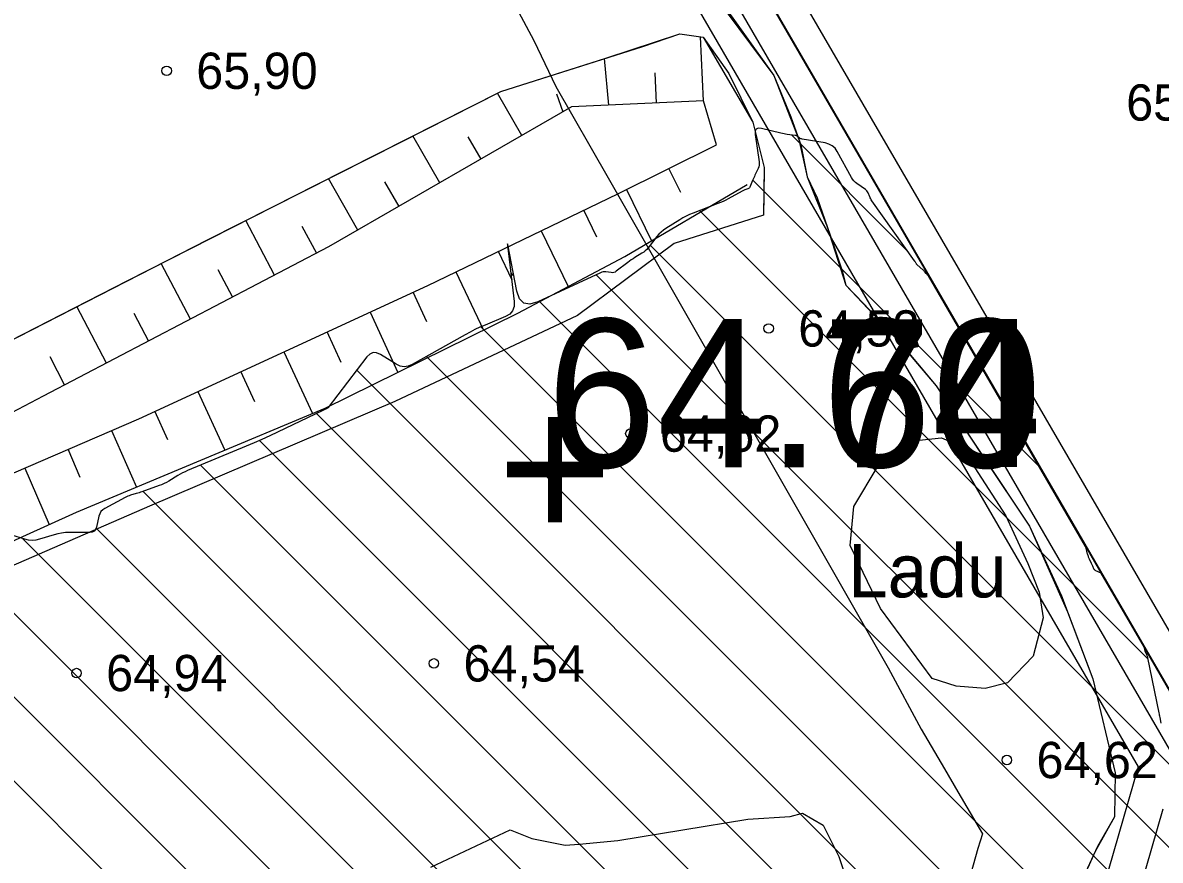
# Model space of a CAD drawing. Extents: x 532503 to 539665, y 6557663 to 6561526.
# Drawn here: x 535410.7 to 535487.5, y 6559863.4 to 6559920 of the extents above; entities that cross this region are included whole.
import ezdxf

# ---------------------------------------------------------------- set-up
doc = ezdxf.new("R2010")
doc.units = 0
for name, color, linetype in [('Default', 7, 'Continuous'), ('HALJASTUS', 7, 'Continuous'), ('illumineerimisjooned', 7, 'Continuous'), ('Kaevandatud ala', 7, 'Continuous'), ('kataster', 7, 'Continuous'), ('KORGUS-EH2000', 7, 'Continuous'), ('MOOTKORG', 7, 'Continuous'), ('MOOTKORGMUU-EH2000', 7, 'Continuous'), ('MOOTMPUNKT', 7, 'Continuous'), ('PIIR_me', 7, 'Continuous'), ('Plokid', 7, 'Continuous'), ('RELJEEF', 7, 'Continuous'), ('TM_aktiivne', 7, 'Continuous')]:
    doc.layers.add(name, color=color, linetype=linetype)

# ---------------------------------------------------------------- blocks, each defined once
blk = doc.blocks.new('POINT_DISPLAY')
at = {"layer": 'Default'}
blk.add_line((0, 0), (0, 0), dxfattribs=at)

msp = doc.modelspace()

# ---------------------------------------------------------------- linework, layer by layer
at = {"layer": 'illumineerimisjooned'}
msp.add_lwpolyline([(534195.15, 6559981.187), (534198.982, 6559981.551), (535160.123, 6560071.768), (535418.528, 6559993.818), (535458.873, 6559929.252), (535494.628, 6559867.696), (535482.599, 6559826.001), (535251.738, 6559649.676), (535250.358, 6559648.526), (535180.445, 6559687.333), (534941.147, 6559814.594), (534876.935, 6559774.719), (534959.617, 6559531.323), (534733.77, 6559483.152), (534375.905, 6559461.866), (534195.514, 6559444.474)], dxfattribs=at)
msp.add_lwpolyline([(534967.673, 6560049.69), (534974.155, 6559828.082), (535058.693, 6559883.051), (535223.499, 6560002.448), (535218.56, 6560049.918), (535415.933, 6559990.422), (535455.447, 6559927.188), (535490.312, 6559867.164), (535479.121, 6559828.379), (535249.574, 6559653.049), (535182.36, 6559690.845), (534940.993, 6559819.216), (534872.135, 6559776.441), (534954.369, 6559534.338), (534950.911, 6559533.67), (534733.22, 6559487.117), (534375.585, 6559465.864), (534199.951, 6559448.922), (533951.788, 6559660.129), (534200.214, 6559977.649), (534931.627, 6560046.309)], close=True, dxfattribs=at)
at = {"layer": 'Kaevandatud ala'}
for p, q in [((535462.619, 6559912.401), (535470.467, 6559904.554)), ((535460.014, 6559909.349), (535479.356, 6559890.008)), ((535456.423, 6559907.284), (535486.727, 6559876.979)), ((535453.091, 6559904.959), (535489.078, 6559868.971)), ((535443.661, 6559903.075), (535443.877, 6559902.859)), ((535449.437, 6559902.956), (535488.971, 6559863.422)), ((535482.493, 6559884.606), (535471.879, 6559902.879)), ((535445.579, 6559901.157), (535487.472, 6559859.264)), ((535441.646, 6559899.433), (535485.59, 6559855.489)), ((535437.981, 6559897.441), (535484.564, 6559850.858)), ((535433.261, 6559896.504), (535480.246, 6559849.52)), ((535430.534, 6559893.574), (535484.456, 6559839.653)), ((535426.695, 6559891.757), (535483.189, 6559835.263)), ((535422.707, 6559890.088), (535481.922, 6559830.872)), ((535418.818, 6559888.32), (535480.343, 6559826.795)), ((535410.701, 6559885.123), (535473.929, 6559821.896)), ((535415.645, 6559885.836), (535477.136, 6559824.345)), ((535405.998, 6559884.169), (535470.721, 6559819.446)), ((535486.467, 6559877.765), (535483.551, 6559882.785)), ((535402.768, 6559881.743), (535467.514, 6559816.996)), ((535398.944, 6559879.91), (535464.307, 6559814.547))]:
    msp.add_line(p, q, dxfattribs=at)
for points in [[(535471.879, 6559902.879), (535471.827, 6559902.926), (535471.797, 6559902.954), (535471.769, 6559902.983), (535471.743, 6559903.014), (535471.718, 6559903.045), (535471.621, 6559903.175), (535471.596, 6559903.207), (535471.569, 6559903.237), (535471.541, 6559903.266), (535471.511, 6559903.293), (535471.119, 6559903.632), (535471.1, 6559903.649), (535471.082, 6559903.668), (535471.066, 6559903.689), (535471.052, 6559903.711), (535470.997, 6559903.8), (535470.983, 6559903.822), (535470.969, 6559903.844), (535470.954, 6559903.866), (535470.939, 6559903.887), (535468.057, 6559907.951), (535468.015, 6559908.013), (535467.978, 6559908.077), (535467.943, 6559908.143), (535467.913, 6559908.211), (535467.799, 6559908.487), (535467.766, 6559908.553), (535467.725, 6559908.612), (535467.676, 6559908.664), (535467.619, 6559908.711), (535467.052, 6559909.109), (535466.943, 6559909.195), (535466.846, 6559909.291), (535466.761, 6559909.398), (535466.687, 6559909.516), (535465.721, 6559911.272), (535465.568, 6559911.492), (535465.381, 6559911.662), (535465.159, 6559911.783), (535464.901, 6559911.854), (535463.339, 6559912.118), (535463.295, 6559912.128), (535463.254, 6559912.143), (535463.216, 6559912.164), (535463.179, 6559912.189), (535463.038, 6559912.301), (535463.001, 6559912.327), (535462.963, 6559912.346), (535462.921, 6559912.36), (535462.878, 6559912.369), (535462.335, 6559912.437), (535462.229, 6559912.451), (535462.125, 6559912.469), (535462.02, 6559912.489), (535461.917, 6559912.512), (535460.604, 6559912.822), (535460.387, 6559912.843), (535460.243, 6559912.783), (535460.171, 6559912.645), (535460.172, 6559912.427), (535460.439, 6559910.576), (535460.447, 6559910.462), (535460.439, 6559910.35), (535460.415, 6559910.24), (535460.374, 6559910.133), (535460.16, 6559909.674), (535460.119, 6559909.586), (535460.079, 6559909.497), (535460.04, 6559909.408), (535460.001, 6559909.319), (535459.814, 6559908.877), (535459.79, 6559908.833), (535459.759, 6559908.797), (535459.721, 6559908.768), (535459.676, 6559908.747), (535459.481, 6559908.679), (535459.433, 6559908.661), (535459.385, 6559908.641), (535459.339, 6559908.619), (535459.293, 6559908.595), (535458.356, 6559908.084), (535458.183, 6559907.993), (535458.007, 6559907.909), (535457.829, 6559907.83), (535457.649, 6559907.756), (535455.977, 6559907.112), (535455.745, 6559907.016), (535455.518, 6559906.909), (535455.296, 6559906.791), (535455.08, 6559906.663), (535454.15, 6559906.081), (535453.98, 6559905.964), (535453.821, 6559905.833), (535453.675, 6559905.689), (535453.54, 6559905.532), (535452.944, 6559904.772), (535452.853, 6559904.665), (535452.753, 6559904.568), (535452.644, 6559904.48), (535452.527, 6559904.402), (535452.043, 6559904.109), (535451.923, 6559904.034), (535451.806, 6559903.955), (535451.69, 6559903.874), (535451.577, 6559903.789), (535450.791, 6559903.184), (535450.714, 6559903.136), (535450.633, 6559903.105), (535450.547, 6559903.092), (535450.457, 6559903.096), (535450.086, 6559903.146), (535449.994, 6559903.152), (535449.904, 6559903.145), (535449.816, 6559903.125), (535449.73, 6559903.092), (535445.49, 6559901.115), (535444.959, 6559900.954), (535444.545, 6559901.022), (535444.248, 6559901.319), (535444.068, 6559901.845), (535443.585, 6559904.404), (535443.49, 6559904.883), (535443.444, 6559905.041), (535443.447, 6559904.877), (535443.501, 6559904.391), (535443.896, 6559901.147), (535443.892, 6559900.806), (535443.791, 6559900.522), (535443.593, 6559900.294), (535443.298, 6559900.123), (535441.923, 6559899.552), (535441.582, 6559899.405), (535441.245, 6559899.247), (535440.914, 6559899.08), (535440.587, 6559898.903), (535436.997, 6559896.889), (535436.725, 6559896.776), (535436.455, 6559896.742), (535436.186, 6559896.787), (535435.92, 6559896.911), (535434.856, 6559897.567), (535434.599, 6559897.68), (535434.362, 6559897.689), (535434.143, 6559897.595), (535433.944, 6559897.399), (535431.333, 6559893.981), (535431.322, 6559893.968), (535431.31, 6559893.957), (535431.296, 6559893.947), (535431.282, 6559893.938), (535431.221, 6559893.906), (535431.206, 6559893.898), (535431.191, 6559893.89), (535431.175, 6559893.883), (535431.16, 6559893.875), (535431.062, 6559893.828), (535431.019, 6559893.807), (535430.976, 6559893.786), (535427.898, 6559892.31), (535427.376, 6559892.064), (535426.851, 6559891.825), (535426.323, 6559891.593), (535425.791, 6559891.368), (535421.821, 6559889.721), (535421.655, 6559889.648), (535421.492, 6559889.569), (535421.332, 6559889.484), (535421.175, 6559889.393), (535420.555, 6559889.016), (535420.397, 6559888.926), (535420.236, 6559888.844), (535420.071, 6559888.77), (535419.902, 6559888.705), (535418.749, 6559888.296), (535418.653, 6559888.262), (535418.557, 6559888.23), (535418.461, 6559888.199), (535418.364, 6559888.169), (535417.976, 6559888.052), (535417.879, 6559888.021), (535417.785, 6559887.984), (535417.693, 6559887.944), (535417.603, 6559887.898), (535416.243, 6559887.172), (535416.095, 6559887.073), (535415.978, 6559886.951), (535415.891, 6559886.805), (535415.835, 6559886.636), (535415.674, 6559885.912), (535415.615, 6559885.754), (535415.52, 6559885.641), (535415.389, 6559885.573), (535415.222, 6559885.549), (535413.834, 6559885.545), (535413.576, 6559885.535), (535413.32, 6559885.505), (535413.067, 6559885.457), (535412.818, 6559885.391), (535411.824, 6559885.086), (535411.576, 6559885.028), (535411.327, 6559885.009), (535411.079, 6559885.028), (535410.83, 6559885.084), (535409.657, 6559885.44)], [(535483.551, 6559882.785), (535483.19, 6559882.958), (535483.149, 6559882.983), (535483.114, 6559883.013), (535483.084, 6559883.049), (535483.061, 6559883.091), (535482.982, 6559883.272), (535482.962, 6559883.317), (535482.941, 6559883.362), (535482.92, 6559883.407), (535482.898, 6559883.451), (535482.754, 6559883.742), (535482.735, 6559883.784), (535482.716, 6559883.827), (535482.699, 6559883.87), (535482.684, 6559883.914), (535482.626, 6559884.092), (535482.612, 6559884.136), (535482.599, 6559884.181), (535482.586, 6559884.226), (535482.575, 6559884.271), (535482.507, 6559884.549), (535482.493, 6559884.606)], [(535487.604, 6559872.655), (535487.53, 6559873.046), (535487.515, 6559873.124), (535487.499, 6559873.202), (535487.484, 6559873.279), (535487.468, 6559873.357), (535486.707, 6559877.076), (535486.696, 6559877.121), (535486.683, 6559877.165), (535486.666, 6559877.208), (535486.647, 6559877.251), (535486.564, 6559877.417), (535486.544, 6559877.459), (535486.528, 6559877.502), (535486.514, 6559877.546), (535486.503, 6559877.591), (535486.467, 6559877.765)]]:
    msp.add_lwpolyline(points, dxfattribs=at)
at = {"layer": 'kataster'}
msp.add_lwpolyline([(533947.7, 6559658.95), (533949.2, 6559955.8), (534198.28, 6559979.48), (535159.89, 6560069.73), (535417.31, 6559992.13), (535457.22, 6559928.24), (535504.86, 6559846.09), (535250.3, 6559650.84), (535181.52, 6559689.04), (534941.15, 6559817.08), (534874.65, 6559775.26), (534957.01, 6559532.73), (534735.22, 6559485.45), (534375.71, 6559463.85), (534199.28, 6559446.9), (534122.84, 6559439.44), (534110.45, 6559447.36), (534092.53, 6559453.94), (534085.13, 6559454.75)], close=True, dxfattribs=at)
msp.add_lwpolyline([(535462.47, 6560012.25), (535491.52, 6559984.18), (535510, 6559958.81), (535524.24, 6559930.97), (535532.62, 6559905.26), (535538.05, 6559871.58), (535504.86, 6559846.09), (535457.22, 6559928.24), (535417.31, 6559992.13)], dxfattribs=at)
at = {"layer": 'KORGUS-EH2000'}
for centre in [(535420.417, 6559916.731), (535461.087, 6559899.326), (535451.743, 6559892.22), (535438.469, 6559876.699), (535414.328, 6559876.047), (535477.18, 6559870.172)]:
    msp.add_circle(centre, 0.32, dxfattribs=at)
at = {"layer": 'PIIR_me'}
msp.add_lwpolyline([(534441.63, 6560002.32), (534688.17, 6560025.46), (534931.44, 6560048.3), (534969.61, 6560051.877), (534976.05, 6559831.7), (535057.56, 6559884.7), (535221.39, 6560003.39), (535216.26, 6560052.7), (535417.23, 6559992.12), (535457.16, 6559928.22), (535492.47, 6559867.43), (535480.86, 6559827.19), (535250.12, 6559650.95), (535250.12, 6559650.95), (535181.4, 6559689.09), (534941.07, 6559816.91), (534874.54, 6559775.58), (534957, 6559532.81), (534951.31, 6559531.71), (534733.49, 6559485.13), (534485.11, 6559470.37)], dxfattribs=at)
at = {"layer": 'Plokid'}
msp.add_line((535486.053, 6559869.718), (535473.831, 6559827.358), dxfattribs=at)
for points in [[(535416.305, 6559985.296), (535453.391, 6559925.949), (535486.053, 6559869.718)], [(535444.178, 6559920.722), (535445.219, 6559918.773), (535446.705, 6559915.669), (535450.253, 6559909.497), (535469.152, 6559876.393), (535471.393, 6559872.262), (535472.97, 6559869.565), (535473.857, 6559868.032), (535475.536, 6559865.196), (535475.21, 6559864.195), (535474.58, 6559861.939)], [(535487.722, 6559866.845), (535477.035, 6559829.805)]]:
    msp.add_lwpolyline(points, dxfattribs=at)
at = {"layer": 'RELJEEF'}
for p, q in [((535456.682, 6559914.697), (535456.488, 6559919.034)), ((535450.288, 6559914.411), (535449.994, 6559917.549)), ((535453.394, 6559916.584), (535453.485, 6559914.554)), ((535444.408, 6559912.366), (535442.762, 6559915.22)), ((535446.76, 6559915.179), (535447.18, 6559913.965)), ((535438.864, 6559909.169), (535437.041, 6559912.33)), ((535440.769, 6559912.271), (535441.636, 6559910.768)), ((535455.148, 6559908.512), (535454.341, 6559910.135)), ((535433.32, 6559905.972), (535431.342, 6559909.449)), ((535435.136, 6559909.227), (535436.092, 6559907.57)), ((535451.476, 6559908.709), (535453.178, 6559905.247)), ((535427.694, 6559902.922), (535425.756, 6559906.624)), ((535449.483, 6559905.481), (535448.597, 6559907.311)), ((535429.544, 6559906.224), (535430.529, 6559904.407)), ((535445.716, 6559905.92), (535447.533, 6559902.153)), ((535443.768, 6559902.594), (535442.834, 6559904.529)), ((535422.025, 6559899.953), (535420.052, 6559903.721)), ((535423.88, 6559903.308), (535424.859, 6559901.438)), ((535439.952, 6559903.138), (535441.828, 6559899.22)), ((535437.992, 6559899.776), (535437.061, 6559901.765)), ((535416.355, 6559896.984), (535414.354, 6559900.805)), ((535418.196, 6559900.366), (535419.19, 6559898.469)), ((535434.155, 6559900.426), (535436.029, 6559896.359)), ((535432.204, 6559897.015), (535431.249, 6559899.086)), ((535412.512, 6559897.423), (535413.52, 6559895.5)), ((535428.343, 6559897.747), (535430.264, 6559893.579)), ((535426.373, 6559894.376), (535425.437, 6559896.407)), ((535422.531, 6559895.067), (535424.355, 6559891.11)), ((535420.498, 6559891.796), (535419.625, 6559893.728)), ((535416.699, 6559892.432), (535418.371, 6559888.61)), ((535414.581, 6559889.266), (535413.761, 6559891.163)), ((535410.824, 6559889.894), (535412.472, 6559886.079))]:
    msp.add_line(p, q, dxfattribs=at)
for points in [[(535453.727, 6559927.191), (535461.427, 6559916.423), (535463.129, 6559912.078), (535463.697, 6559909.562), (535465.015, 6559906.249), (535466.294, 6559902.238), (535469.637, 6559898.724), (535472.402, 6559895.44), (535478.697, 6559885.972), (535481.272, 6559880.178), (535482.989, 6559875.651), (535484.486, 6559869.301), (535484.458, 6559866.344), (535483.143, 6559863.981), (535482.62, 6559862.849)], [(535458.288, 6559920.64), (535461.427, 6559916.423), (535462.577, 6559913.609), (535463.256, 6559911.725), (535463.697, 6559909.562), (535464.355, 6559908.137), (535465.392, 6559905.172), (535466.073, 6559903.142), (535466.294, 6559902.238), (535467.521, 6559900.984), (535469.883, 6559898.462), (535472.402, 6559895.44), (535475.669, 6559890.51), (535478.697, 6559885.972), (535480.86, 6559881.264), (535482.989, 6559875.651), (535484.486, 6559869.301), (535484.458, 6559866.344), (535483.305, 6559864.332), (535481.821, 6559861.119)], [(535268.305, 6559823.159), (535267.143, 6559826.834), (535272.404, 6559831.585), (535289.68, 6559839.949), (535302.148, 6559844.707), (535317.414, 6559850.514), (535333.985, 6559859.122), (535351.403, 6559869.313), (535362.528, 6559875.902), (535372.208, 6559880.134), (535383.73, 6559886.487), (535401.215, 6559894.081), (535423.165, 6559905.314), (535436.227, 6559911.919), (535442.986, 6559915.333), (535452.592, 6559918.371), (535455.084, 6559919.225), (535456.662, 6559919.01), (535458.391, 6559916.556), (535460.015, 6559913.27), (535460.79, 6559910.193), (535460.753, 6559908.289), (535460.731, 6559906.968)], [(535340.1, 6559862.7), (535362.528, 6559875.902), (535372.208, 6559880.134), (535383.73, 6559886.487), (535388.308, 6559888.475), (535401.215, 6559894.081), (535415.073, 6559901.173), (535417.788, 6559902.562), (535430.482, 6559909.014), (535442.986, 6559915.333), (535450.087, 6559917.579), (535455.084, 6559919.225), (535456.662, 6559919.01), (535460.015, 6559913.27), (535460.79, 6559910.193), (535460.731, 6559906.968)], [(535456.682, 6559914.697), (535447.758, 6559914.298), (535431.355, 6559904.839), (535412.08, 6559894.746), (535398.777, 6559887.767), (535373.397, 6559875.08), (535358.248, 6559868.017), (535332.79, 6559855.036), (535318.006, 6559849.212), (535301.23, 6559838.268)], [(535301.316, 6559838.321), (535319.676, 6559842.764), (535335.912, 6559850.534), (535365.349, 6559866.751), (535390.517, 6559881.121), (535418.525, 6559893.221), (535438.063, 6559902.227), (535450.89, 6559908.417), (535457.559, 6559911.737), (535456.682, 6559914.697)], [(535294.283, 6559826.645), (535295.349, 6559827.591), (535297.121, 6559828.289), (535301.55, 6559830.375), (535305.415, 6559832.206), (535312.97, 6559834.349), (535319.979, 6559837.341), (535325.181, 6559839.338), (535338.102, 6559846.328), (535357.195, 6559858.163), (535373.547, 6559867.03), (535385.523, 6559873.077), (535401.737, 6559881.208), (535414.334, 6559886.924), (535431.116, 6559893.935), (535444.139, 6559900.361), (535451.376, 6559904.182), (535459.627, 6559909.059)], [(535460.731, 6559906.968), (535454.708, 6559905.059), (535448.179, 6559900.209), (535435.824, 6559894.386), (535419.259, 6559887.317), (535404.323, 6559880.832), (535391.453, 6559874.256), (535373.092, 6559864.667), (535361.49, 6559858.593), (535347.558, 6559849.98), (535338.79, 6559844.299), (535333.31, 6559840.796), (535328.041, 6559838.778), (535314.752, 6559832.41), (535310.233, 6559830.841), (535303.523, 6559829.521), (535297.419, 6559826.994), (535296.43, 6559826.431), (535298.079, 6559822.89), (535299.832, 6559815.625), (535300.781, 6559810.773), (535301.702, 6559804.416), (535301.401, 6559802.543), (535299.456, 6559800.282)], [(535460.731, 6559906.968), (535454.708, 6559905.059), (535448.179, 6559900.209), (535435.824, 6559894.386), (535419.259, 6559887.317), (535404.323, 6559880.832), (535391.453, 6559874.256), (535373.092, 6559864.667), (535361.49, 6559858.593), (535347.558, 6559849.98), (535338.79, 6559844.299), (535333.31, 6559840.796), (535328.041, 6559838.778), (535314.752, 6559832.41), (535310.233, 6559830.841), (535303.523, 6559829.521), (535297.419, 6559826.994), (535296.43, 6559826.431), (535298.079, 6559822.89), (535299.832, 6559815.625), (535300.781, 6559810.773), (535301.702, 6559804.416), (535301.401, 6559802.543), (535299.456, 6559800.282)], [(535479.641, 6559879.787), (535478.964, 6559877.198), (535477.214, 6559875.393), (535475.714, 6559874.998), (535473.758, 6559875.162), (535472.124, 6559875.688), (535468.648, 6559880.413), (535466.589, 6559884.666), (535466.849, 6559887.305), (535468.481, 6559890.055), (535470.824, 6559891.738), (535472.772, 6559891.945), (535474.059, 6559891.374), (535477.101, 6559886.665), (535478.587, 6559883.446), (535479.354, 6559881.505), (535479.641, 6559879.787)], [(535479.641, 6559879.787), (535478.964, 6559877.198), (535477.214, 6559875.393), (535475.714, 6559874.998), (535473.758, 6559875.162), (535472.124, 6559875.688), (535468.648, 6559880.413), (535466.589, 6559884.666), (535466.849, 6559887.305), (535468.481, 6559890.055), (535470.824, 6559891.738), (535472.772, 6559891.945), (535474.059, 6559891.374), (535477.101, 6559886.665), (535478.587, 6559883.446), (535479.354, 6559881.505), (535479.641, 6559879.787)], [(535438.255, 6559862.942), (535443.621, 6559865.449), (535445.08, 6559864.876), (535447.345, 6559864.411), (535448.283, 6559864.481), (535450.896, 6559864.724), (535459.689, 6559866.185), (535462.535, 6559866.352), (535463.378, 6559866.586), (535464.764, 6559865.775), (535465.836, 6559863.664), (535466.41, 6559861.865)]]:
    msp.add_lwpolyline(points, dxfattribs=at)
at = {"layer": 'TM_aktiivne'}
msp.add_lwpolyline([(535159.92, 6560069.74), (535417.23, 6559992.12), (535457.16, 6559928.22), (535492.47, 6559867.43), (535480.86, 6559827.19), (535250.49, 6559651.24), (535250.13, 6559650.94), (535181.4, 6559689.09), (534941.07, 6559816.9), (534874.53, 6559775.58), (534957, 6559532.81), (534733.5, 6559485.14), (534375.75, 6559463.86), (534199.32, 6559446.85), (534124.95, 6559439.68), (533949.03, 6559659.85), (533949.15, 6559955.79), (534199.17, 6559979.56)], close=True, dxfattribs=at)

# ---------------------------------------------------------------- block references
at = {"layer": 'MOOTKORGMUU-EH2000'}
for p in [(535446.082, 6559889.945), (535446.083, 6559889.965)]:
    msp.add_blockref('POINT_DISPLAY', p, dxfattribs=at)

# ---------------------------------------------------------------- texts
at = {"layer": 'HALJASTUS'}
msp.add_text('Ladu', height=3.6, dxfattribs=at).set_placement((535466.449, 6559881.158))
at = {"layer": 'KORGUS-EH2000'}
for s, p in [('65,90 ', (535422.417, 6559915.506)), ('65,50', (535485.24, 6559913.363)), ('64,53 ', (535463.087, 6559898.101)), ('64,62 ', (535453.743, 6559890.995)), ('64,54 ', (535440.469, 6559875.474)), ('64,94 ', (535416.328, 6559874.822)), ('64,62 ', (535479.18, 6559868.947))]:
    msp.add_text(s, height=2.45, dxfattribs=at).set_placement(p)
at = {"layer": 'MOOTKORG'}
for s, p in [('64.70', (535446.082, 6559889.945)), ('64.64', (535446.083, 6559889.965))]:
    msp.add_text(s, height=10, dxfattribs=at).set_placement(p)
at = {"layer": 'MOOTMPUNKT'}
for p in [(535442.749, 6559884.945), (535442.75, 6559884.965)]:
    msp.add_text('+', height=10, dxfattribs=at).set_placement(p)

doc.saveas('drawing.dxf')
